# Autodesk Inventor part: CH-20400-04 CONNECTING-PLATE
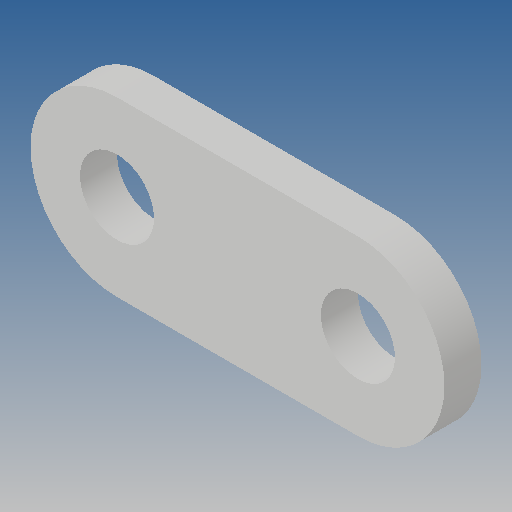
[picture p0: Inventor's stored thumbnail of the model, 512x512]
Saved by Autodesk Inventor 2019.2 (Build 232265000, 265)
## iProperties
Created: 2012-09
Part Number: CH-20400-04 CONNECTING-PLATE
Material: Ogólny
Document SubType Name: Modeling
Designer: CADENGINEERING4
Density: 1 g/cm^3
Appearance: Domyślna
Author: CADENGINEERING4
Revision Number: ÈÎºÎ
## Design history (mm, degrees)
feature "À­Éì1"
node "Bryła1"
